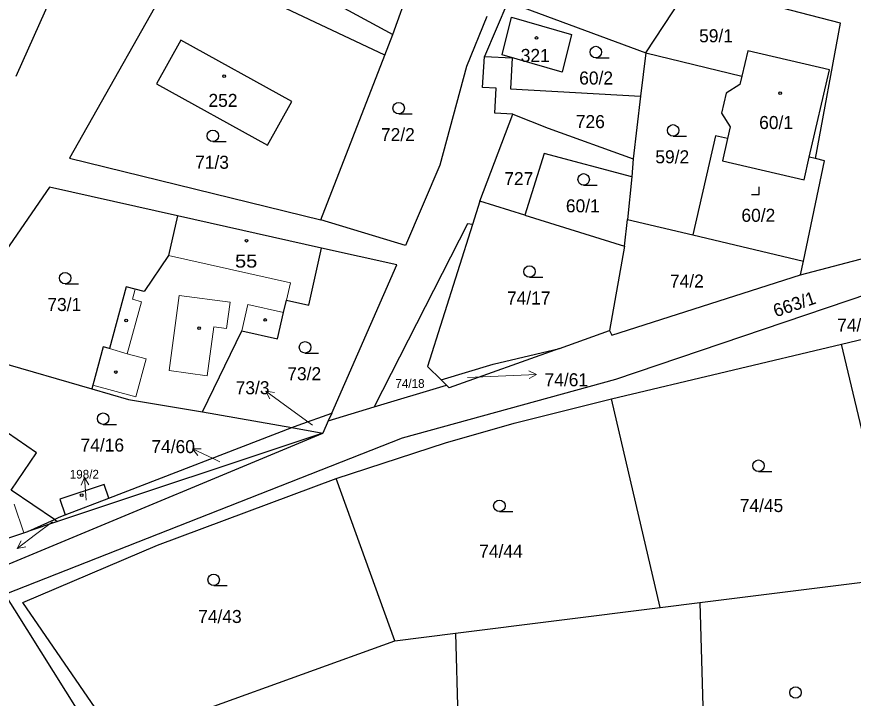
# Model space of a CAD drawing. Extents: x -758887 to -754328, y -1031688 to -1029144.
# Drawn here: x -756515.3 to -756406, y -1030649.6 to -1030560.6 of the extents above; entities that cross this region are included whole.
import ezdxf
from ezdxf.enums import TextEntityAlignment as Align

# ---------------------------------------------------------------- set-up
doc = ezdxf.new("R2010")
doc.units = 0
doc.header["$LTSCALE"] = 0.68
for name, color, linetype, lineweight in [('1', 7, 'Continuous', 25), ('3', 7, 'Continuous', 25), ('4', 7, 'Continuous', 13), ('5', 7, 'Continuous', 25), ('7', 7, 'Continuous', 13)]:
    doc.layers.add(name, color=color, linetype=linetype, lineweight=lineweight)
doc.layers.add('2', color=7, linetype='Continuous')

msp = doc.modelspace()

# ---------------------------------------------------------------- linework, layer by layer
at = {"layer": '1'}
for p, q in [((-756467.23, -1030565.61), (-756493.78, -1030553.1)), ((-756451.15, -1030558.65), (-756454.23, -1030565.79)), ((-756467.23, -1030565.61), (-756466.18, -1030562.91)), ((-756433.14, -1030565.31), (-756420.59, -1030568.38)), ((-756475.62, -1030587.14), (-756467.23, -1030565.61)), ((-756454.81, -1030584.7), (-756450.51, -1030573.35)), ((-756410.96, -1030579.14), (-756411.76, -1030578.96)), ((-756435.54, -1030587.1), (-756426.98, -1030589.11)), ((-756412.92, -1030594.32), (-756392.38, -1030588.89)), ((-756435.91, -1030590.57), (-756437.87, -1030601.58)), ((-756412.92, -1030594.32), (-756412.54, -1030592.51)), ((-756444.4, -1030603.92), (-756437.87, -1030601.58)), ((-756525.31, -1030603.49), (-756505.53, -1030609.22)), ((-756437.63, -1030610.53), (-756407.55, -1030603.37)), ((-756459.18, -1030608.72), (-756459.86, -1030608.05)), ((-756468.64, -1030611.57), (-756459.18, -1030608.72)), ((-756431.26, -1030637.77), (-756437.63, -1030610.53)), ((-756491.06, -1030612.22), (-756479.4, -1030614.27)), ((-756474.63, -1030613.38), (-756468.64, -1030611.57)), ((-756503.31, -1030623.47), (-756479.4, -1030614.27)), ((-756479.4, -1030614.27), (-756475.34, -1030614.99)), ((-756475.34, -1030614.99), (-756510, -1030626.53)), ((-756510.42, -1030626.25), (-756516.05, -1030622.42)), ((-756509.01, -1030625.66), (-756503.31, -1030623.47)), ((-756513.91, -1030627.83), (-756510.42, -1030626.25)), ((-756510, -1030626.53), (-756513.91, -1030627.83)), ((-756510.42, -1030626.25), (-756510, -1030626.53)), ((-756426.06, -1030637.12), (-756425.23, -1030667.33)), ((-756465.93, -1030642.12), (-756457.99, -1030641.12)), ((-756457.99, -1030641.12), (-756457.25, -1030668.21))]:
    msp.add_line(p, q, dxfattribs=at)
for points in [[(-756445.29, -1030545.09), (-756448.93, -1030553.51), (-756450.46, -1030557.04), (-756451.15, -1030558.65), (-756433.14, -1030565.31), (-756427.23, -1030556.37), (-756424.9, -1030552.84), (-756430.63, -1030551.42)], [(-756515.42, -1030568.35), (-756510.82, -1030558), (-756529.65, -1030550)], [(-756486.69, -1030551.79), (-756466.18, -1030562.91), (-756463.96, -1030556.71), (-756461.87, -1030550.85)], [(-756312.59, -1030555.25), (-756315.52, -1030551.79), (-756381.49, -1030591.35), (-756401.18, -1030595.86), (-756437.11, -1030607.98), (-756464.98, -1030615.64), (-756516.89, -1030636.06), (-756515.63, -1030638.06), (-756495.42, -1030670.29), (-756493.95, -1030672.9)], [(-756493.78, -1030553.1), (-756508.46, -1030579.07), (-756475.62, -1030587.14)], [(-756410.96, -1030579.14), (-756407.69, -1030561.45), (-756427.23, -1030556.37)], [(-756453.91, -1030560.56), (-756456.58, -1030567.12), (-756460.05, -1030579.99), (-756464.55, -1030590.48), (-756475.62, -1030587.14)], [(-756433.14, -1030565.31), (-756433.82, -1030570.98), (-756434.8, -1030579.16), (-756434.94, -1030581.51), (-756435.54, -1030587.1)], [(-756411.76, -1030578.96), (-756409.14, -1030567.54), (-756419.81, -1030565.06), (-756420.59, -1030568.38)], [(-756450.51, -1030573.35), (-756452.85, -1030573.22), (-756452.67, -1030569.93), (-756454.45, -1030569.83), (-756454.23, -1030565.79)], [(-756454.23, -1030565.79), (-756450.58, -1030565.99), (-756450.81, -1030570.03), (-756433.82, -1030570.98)], [(-756420.59, -1030568.38), (-756420.84, -1030569.46), (-756422.62, -1030570.6), (-756423.24, -1030573.22), (-756422.1, -1030575), (-756422.44, -1030576.5)], [(-756450.51, -1030573.35), (-756445.88, -1030575.17), (-756434.8, -1030579.16)], [(-756422.44, -1030576.5), (-756424.02, -1030576.14), (-756426.98, -1030589.11), (-756412.54, -1030592.51)], [(-756422.44, -1030576.5), (-756423.11, -1030579.41), (-756412.44, -1030581.9), (-756411.76, -1030578.96)], [(-756434.94, -1030581.51), (-756446.43, -1030578.45), (-756448.94, -1030586.52), (-756435.91, -1030590.57), (-756435.54, -1030587.1)], [(-756412.54, -1030592.51), (-756409.76, -1030579.42), (-756410.96, -1030579.14)], [(-756494.34, -1030586.61), (-756511.08, -1030582.87), (-756525.31, -1030603.49)], [(-756448.94, -1030586.52), (-756454.81, -1030584.7), (-756455.78, -1030587.76)], [(-756494.34, -1030586.61), (-756495.5, -1030591.79), (-756498.69, -1030596.51), (-756499.85, -1030596.2), (-756501.04, -1030595.88), (-756503.22, -1030603.94), (-756504.04, -1030603.72), (-756505.4, -1030608.74), (-756505.53, -1030609.22)], [(-756491.06, -1030612.22), (-756485.91, -1030601.62), (-756481.27, -1030602.66), (-756480.46, -1030599.25), (-756480.1, -1030597.64), (-756477.17, -1030598.29), (-756475.5, -1030590.83), (-756494.34, -1030586.61)], [(-756455.78, -1030587.76), (-756456.41, -1030587.67), (-756468.64, -1030611.57)], [(-756455.78, -1030587.76), (-756461.64, -1030606.29), (-756459.86, -1030608.05)], [(-756474.18, -1030612.37), (-756465.65, -1030593.03), (-756475.5, -1030590.83)], [(-756437.87, -1030601.58), (-756437.55, -1030602.2), (-756412.92, -1030594.32)], [(-756407.55, -1030603.37), (-756397.34, -1030600.94), (-756388.34, -1030598.58), (-756382.69, -1030596.68)], [(-756516.05, -1030622.42), (-756512.74, -1030617.55), (-756519.11, -1030613.23), (-756516.54, -1030609.45), (-756525.31, -1030603.49)], [(-756457.99, -1030641.12), (-756431.26, -1030637.77), (-756426.06, -1030637.12), (-756400.29, -1030633.88), (-756407.55, -1030603.37)], [(-756459.86, -1030608.05), (-756453.06, -1030605.98), (-756444.4, -1030603.92)], [(-756444.4, -1030603.92), (-756458.81, -1030609.08), (-756459.18, -1030608.72)], [(-756505.53, -1030609.22), (-756500.72, -1030610.61), (-756491.06, -1030612.22)], [(-756473.6, -1030620.91), (-756459.31, -1030616.27), (-756450.33, -1030613.71), (-756437.63, -1030610.53)], [(-756479.4, -1030614.27), (-756478.56, -1030613.95), (-756474.18, -1030612.37)], [(-756474.18, -1030612.37), (-756474.63, -1030613.38), (-756475.34, -1030614.99)], [(-756525.65, -1030631.75), (-756545.81, -1030638.46), (-756547.04, -1030637.4), (-756553.18, -1030645.21), (-756551.08, -1030646.53), (-756475.34, -1030614.99)], [(-756502.13, -1030655.2), (-756514.55, -1030637.12), (-756496.93, -1030629.62), (-756473.6, -1030620.91)], [(-756502.13, -1030655.2), (-756465.93, -1030642.12), (-756473.6, -1030620.91)], [(-756503.31, -1030623.47), (-756503.9, -1030621.71), (-756509.69, -1030623.63), (-756509.01, -1030625.66)], [(-756510.42, -1030626.25), (-756509.79, -1030625.96), (-756509.01, -1030625.66)], [(-756525.65, -1030631.75), (-756514.41, -1030628), (-756513.91, -1030627.83)]]:
    msp.add_lwpolyline(points, dxfattribs=at)
for points in [[(-756444.07, -1030567.86), (-756451.91, -1030565.58), (-756450.7, -1030560.65), (-756442.85, -1030562.93)], [(-756482.56, -1030577.37), (-756479.37, -1030571.66), (-756493.91, -1030563.67), (-756497.09, -1030569.38)]]:
    msp.add_lwpolyline(points, close=True, dxfattribs=at)
at = {"layer": '3'}
for p, q in [((-756439.653, -1030565.97), (-756437.903, -1030565.97)), ((-756465.423, -1030573.3), (-756463.673, -1030573.3)), ((-756429.563, -1030576.2), (-756427.813, -1030576.2)), ((-756489.713, -1030576.91), (-756487.963, -1030576.91)), ((-756441.253, -1030582.6), (-756439.503, -1030582.6)), ((-756448.323, -1030594.64), (-756446.573, -1030594.64)), ((-756509.023, -1030595.49), (-756507.273, -1030595.49)), ((-756477.663, -1030604.53), (-756475.913, -1030604.53)), ((-756504.053, -1030613.85), (-756502.303, -1030613.85)), ((-756418.393, -1030620), (-756416.643, -1030620)), ((-756452.263, -1030625.23), (-756450.513, -1030625.23)), ((-756489.603, -1030634.91), (-756487.853, -1030634.91))]:
    msp.add_line(p, q, dxfattribs=at)
msp.add_lwpolyline([(-756419.321, -1030583.84), (-756418.32, -1030583.84), (-756418.32, -1030582.84)], dxfattribs=at)
for centre in [(-756439.6529, -1030565.2198), (-756465.4229, -1030572.5498), (-756429.5629, -1030575.4498), (-756489.7129, -1030576.1598), (-756441.2529, -1030581.8498), (-756448.3229, -1030593.8898), (-756509.0229, -1030594.7398), (-756477.6629, -1030603.7798), (-756504.0529, -1030613.0998), (-756418.3929, -1030619.2498), (-756452.2629, -1030624.4798), (-756489.6029, -1030634.1598), (-756413.5529, -1030648.8698)]:
    msp.add_circle(centre, 0.75, dxfattribs=at)
at = {"layer": '4'}
for p, q in [((-756499.85, -1030596.2), (-756500.2, -1030597.51)), ((-756494.1, -1030597.02), (-756487.46, -1030597.9)), ((-756499.04, -1030597.82), (-756500.89, -1030604.62)), ((-756500.2, -1030597.51), (-756499.04, -1030597.82)), ((-756487.91, -1030601.32), (-756487.46, -1030597.9)), ((-756485.91, -1030601.62), (-756485.14, -1030598.2)), ((-756480.46, -1030599.25), (-756485.14, -1030598.2)), ((-756490.44, -1030607.49), (-756489.59, -1030601.09)), ((-756489.59, -1030601.09), (-756487.91, -1030601.32)), ((-756503.22, -1030603.94), (-756500.89, -1030604.62)), ((-756500.89, -1030604.62), (-756498.43, -1030605.29)), ((-756498.43, -1030605.29), (-756499.78, -1030610.26)), ((-756505.4, -1030608.74), (-756499.78, -1030610.26)), ((-756515.66, -1030624.25), (-756514.41, -1030628))]:
    msp.add_line(p, q, dxfattribs=at)
for points in [[(-756495.5, -1030591.79), (-756479.58, -1030595.35), (-756480.1, -1030597.64)], [(-756490.44, -1030607.49), (-756495.4, -1030606.83), (-756494.1, -1030597.02)]]:
    msp.add_lwpolyline(points, dxfattribs=at)
at = {"layer": '5'}
for centre in [(-756447.4068, -1030563.3792), (-756488.2468, -1030568.3592), (-756415.5768, -1030570.5792), (-756485.3068, -1030589.8592), (-756501.0368, -1030600.2692), (-756482.8868, -1030600.2092), (-756491.5168, -1030601.2692), (-756502.3968, -1030607.0092), (-756506.8568, -1030623.0892)]:
    msp.add_circle(centre, 0.175, dxfattribs=at)
at = {"layer": '7'}
for p, q in [((-756447.403, -1030607.313), (-756448.429, -1030606.865)), ((-756482.778, -1030609.516), (-756482.262, -1030610.51)), ((-756492.37, -1030617.052), (-756491.674, -1030617.929)), ((-756506.489, -1030620.766), (-756506.919, -1030621.8)), ((-756515.267, -1030630.056), (-756514.166, -1030629.853))]:
    msp.add_line(p, q, dxfattribs=at)
for points in [[(-756456.45, -1030607.74), (-756450.4, -1030607.47), (-756447.403, -1030607.313), (-756448.377, -1030607.865)], [(-756476.69, -1030613.97), (-756480.35, -1030611.28), (-756482.778, -1030609.516), (-756481.673, -1030609.7)], [(-756488.78, -1030618.73), (-756489.65, -1030618.32), (-756492.37, -1030617.052), (-756491.251, -1030617.021)], [(-756506.28, -1030623.76), (-756506.489, -1030620.766), (-756505.92, -1030621.73)], [(-756510.67, -1030626.59), (-756512.87, -1030628.25), (-756515.267, -1030630.056), (-756514.768, -1030629.053)]]:
    msp.add_lwpolyline(points, dxfattribs=at)

# ---------------------------------------------------------------- texts
at = {"layer": '2'}
for s, height, p in [('59/1', 1.7, (-756423.95, -1030563.94)), ('321', 1.7, (-756447.579, -1030566.51)), ('60/2', 1.7, (-756439.62, -1030569.46)), ('252', 1.7, (-756488.389, -1030572.38)), ('726', 1.7, (-756440.379, -1030575.15)), ('60/1', 1.7, (-756416.1, -1030575.27)), ('72/2', 1.7, (-756465.53, -1030576.85)), ('59/2', 1.7, (-756429.67, -1030579.75)), ('71/3', 1.7, (-756489.82, -1030580.46)), ('727', 1.7, (-756449.729, -1030582.6)), ('60/1', 1.7, (-756441.36, -1030586.15)), ('60/2', 1.7, (-756418.42, -1030587.39)), ('74/2', 1.7, (-756427.76, -1030595.98)), ('74/17', 1.7, (-756448.43, -1030598.19)), ('73/1', 1.7, (-756509.13, -1030599.04)), ('74/14', 1.7, (-756405.28, -1030601.73)), ('73/2', 1.7, (-756477.77, -1030608.08)), ('74/18', 1.14, (-756463.949, -1030609.08)), ('74/61', 1.7, (-756443.52, -1030608.87)), ('73/3', 1.7, (-756484.52, -1030609.91)), ('74/16', 1.7, (-756504.16, -1030617.4)), ('74/60', 1.7, (-756494.9, -1030617.6)), ('198/2', 1.14, (-756506.509, -1030620.93)), ('74/45', 1.7, (-756418.01, -1030625.3)), ('74/44', 1.7, (-756452.06, -1030631.27)), ('74/43', 1.7, (-756488.79, -1030639.79))]:
    msp.add_text(s, height=height, dxfattribs=at).set_placement(p, align=Align.CENTER)
at = {"layer": '2', "width": 1.15}
msp.add_text('55', height=1.7, dxfattribs=at).set_placement((-756485.36, -1030593.37), align=Align.CENTER)
at = {"layer": '2'}
msp.add_text('663/1', height=1.7, rotation=19, dxfattribs=at).set_placement((-756413.4382, -1030598.9496), align=Align.CENTER)

doc.saveas('drawing.dxf')
